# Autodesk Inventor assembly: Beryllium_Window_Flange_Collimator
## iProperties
Shininess: 64.0
Length Units: 11269
Angle Units: 11279
Time Units: 11290
Mass Units: 11283
Length Display Precision: 3
Angle Display Precision: 2
Compacted: True
Created: 2004-07
Part Number: Beryllium_Window_Flange_Collimator
Document SubType Name: Assembly
Designer: John Blackburn
Manufacturer: Standard
Standards Organization: Custom
Density: 0.0
Volumn: 0.0
Area: 0.0
PropertySet Name: Model Information
Control State: 0
Master: False
Checked Out: False
Author: John Blackburn
